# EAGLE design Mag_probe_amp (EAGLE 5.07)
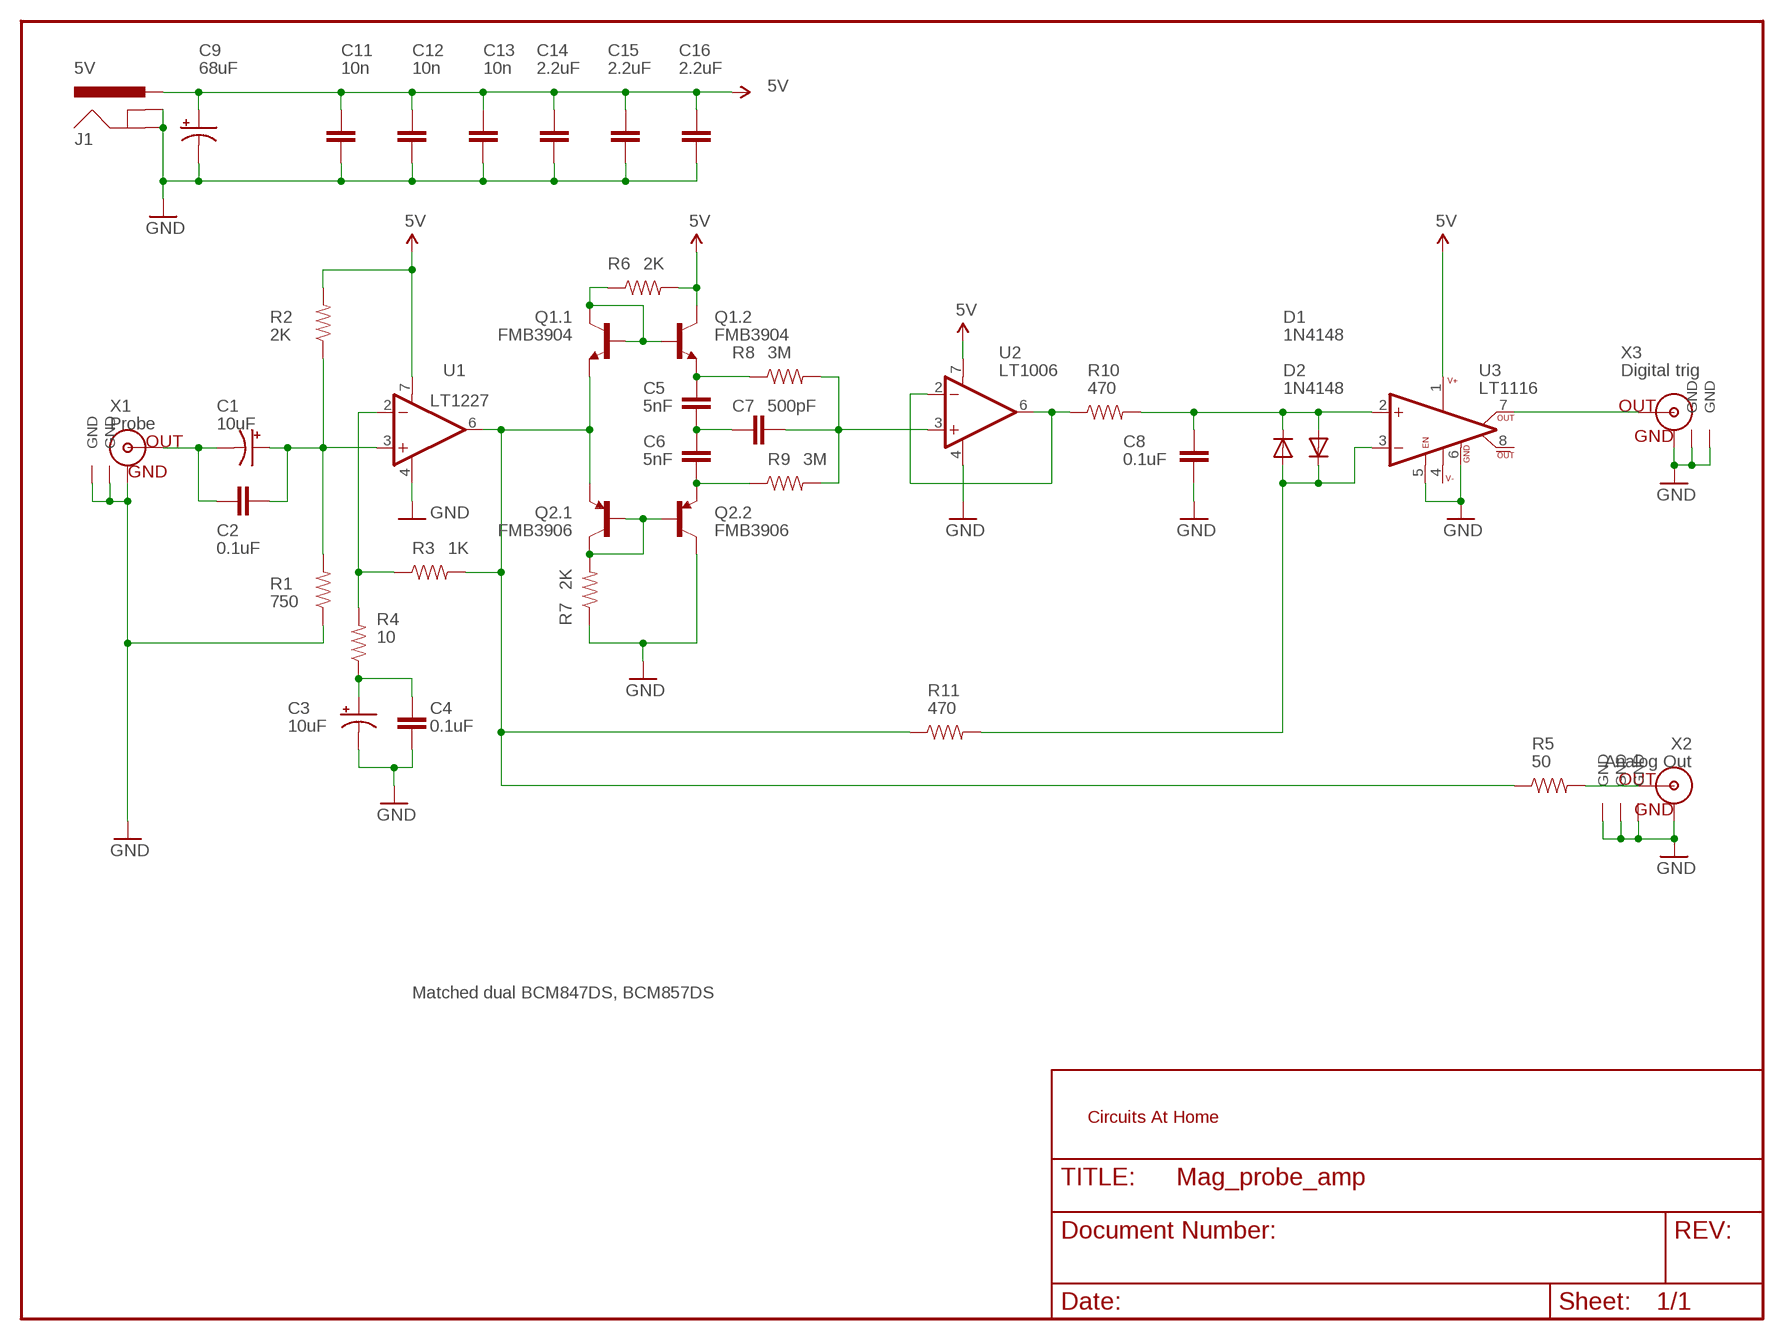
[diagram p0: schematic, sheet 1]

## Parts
C1  10uF  CAP_POL1206  [EIA3216]
C2  0.1uF  CAP1206  [1206]
C3  10uF  CAP_POL1206  [EIA3216]
C4  0.1uF  CAP1206  [1206]
C5  5nF  CAP1206  [1206]
C6  5nF  CAP1206  [1206]
C7  500pF  CAP1206  [1206]
C8  0.1uF  CAP1206  [1206]
C9  68uF  CAP_POL7343  [EIA7343]
C11  10n  CAP1206  [1206]
C12  10n  CAP1206  [1206]
C13  10n  CAP1206  [1206]
C14  2.2uF  CAP1206  [1206]
C15  2.2uF  CAP1206  [1206]
C16  2.2uF  CAP1206  [1206]
D1  1N4148  DIODE-SOD123  [SOD-123]
D2  1N4148  DIODE-SOD123  [SOD-123]
J1  5V  POWER_JACKPTH_LOCK  [POWER_JACK_PTH_LOCK]
Q1  FMB3904  NPN-DUAL-SOT  [SOT23-6]
Q2  FMB3906  PNP-DUAL-SOT  [SOT23-6]
R1  750  RESISTOR1206  [1206]
R2  2K  RESISTOR1206  [1206]
R3  1K  RESISTOR1206  [1206]
R4  10  RESISTOR1206  [1206]
R5  50  RESISTOR1206  [1206]
R6  2K  RESISTOR1206  [1206]
R7  2K  RESISTOR1206  [1206]
R8  3M  RESISTOR1206  [1206]
R9  3M  RESISTOR1206  [1206]
R10  470  RESISTOR1206  [1206]
R11  470  RESISTOR1206  [1206]
U1  LT1227  LT1227_5PIN  [SO08]
U2  LT1006  LT1006_5PIN-SO  [SO08]
U3  LT1116  LT1116_SO8  [SO08]
X1  Probe  BNC-PTHRA  [BNC]
X2  Analog Out  SMB  [SMB_PCB]
X3  Digital trig  BNC-PTHRA  [BNC]

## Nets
5V: C9.A(+) C11.1 C12.1 C13.1 C14.1 C15.1 C16.1 J1.PWR Q1.4(.2:C) R2.2 R6.2 U1.7(V+) U2.7(V+) U3.1(V+)
GND: C3.C(-) C4.2 C8.2 C9.C(-) C11.2 C12.2 C13.2 C14.2 C15.2 C16.2 J1.GND J1.GNDBREAK Q2.4(.2:C) R1.1 R7.1 U1.4(V-) U2.4(V-) U3.5(LA_EN) U3.6(GND) X1.3(GND) X1.4(GND) X1.GND X2.GND1(GND) X2.GND2(GND) X2.GND3(GND) X2.GND4(GND) X3.3(GND) X3.4(GND) X3.GND
N$1: C3.A(+) C4.1 R4.1
N$2: R10.1 U2.2(-) U2.6(OUT)
N$3: R3.1 R4.2 U1.2(-)
N$5: C1.C(-) C2.1 X1.S(OUT)
N$6: R5.2 X2.CENTER(OUT)
N$7: Q1.1(.1:B) Q1.3(.2:B) Q1.6(.1:C) R6.1
N$9: C8.1 D1.K(C) D2.A R10.2 U3.2(+IN)
N$10: D1.A D2.K(C) R11.2 U3.3(-IN)
N$11: Q2.1(.1:B) Q2.3(.2:B) Q2.6(.1:C) R7.2
N$12: U3.7(OUT) X3.S(OUT)
N$13: C5.1 Q1.2(.2:E) R8.1
N$15: C6.2 Q2.2(.2:E) R9.1
N$16: C5.2 C6.1 C7.1
N$17: C7.2 R8.2 R9.2 U2.3(+)
U1_3: C1.A(+) C2.2 R1.2 R2.1 U1.3(+)
U1_6: Q1.5(.1:E) Q2.5(.1:E) R3.2 R5.1 R11.1 U1.6(OUT)
Unconnected: U3.8(!OUT)

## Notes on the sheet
- Matched dual BCM847DS, BCM857DS

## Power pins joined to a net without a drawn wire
V-: U3.4(V-)

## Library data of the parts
C1 C3 C9 = CH_passive:CAP_POL: Capacitor Polarized
C2 C4-C8 C11-C16 = CH_passive:CAP: Capacitor
D1 D2 = CH_semiconductors:DIODE: Diode
J1 = CH_connectors:POWER_JACK: Power Jack This is the standard 5.5mm barrel jack for power. The PTH is the most common, proven, reliable, footprint. All others are experimental. The Slot footprint only works if the mill layer is transmitted to the PCB fab house so be warned. Spark Fun Electronics SKU : PRT-00119. Mating wall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
Q1 = CH_semiconductors:NPN-DUAL: Dual 2N3904 Fairchild FMB3904 SOT23-6 package
Q2 = CH_semiconductors:PNP-DUAL: Dual 2N3906 Fairchild FMB3906
R1-R11 = CH_passive:RESISTOR: Resistor
U1 = CH_Linear_technology:LT1227_5PIN: Linear Technology 140MHz Video Current Feedback Amplifier
U2 = CH_Linear_technology:LT1006_5PIN: LT1006 precision single supply op amp
U3 = CH_Linear_technology:LT1116: LT1116 12ns, Single Supply Ground-Sensing Comparator
X1 X3 = CH_connectors:BNC: BNC Connector, Mouser Part# 5227161
X2 = CH_connectors:SMB

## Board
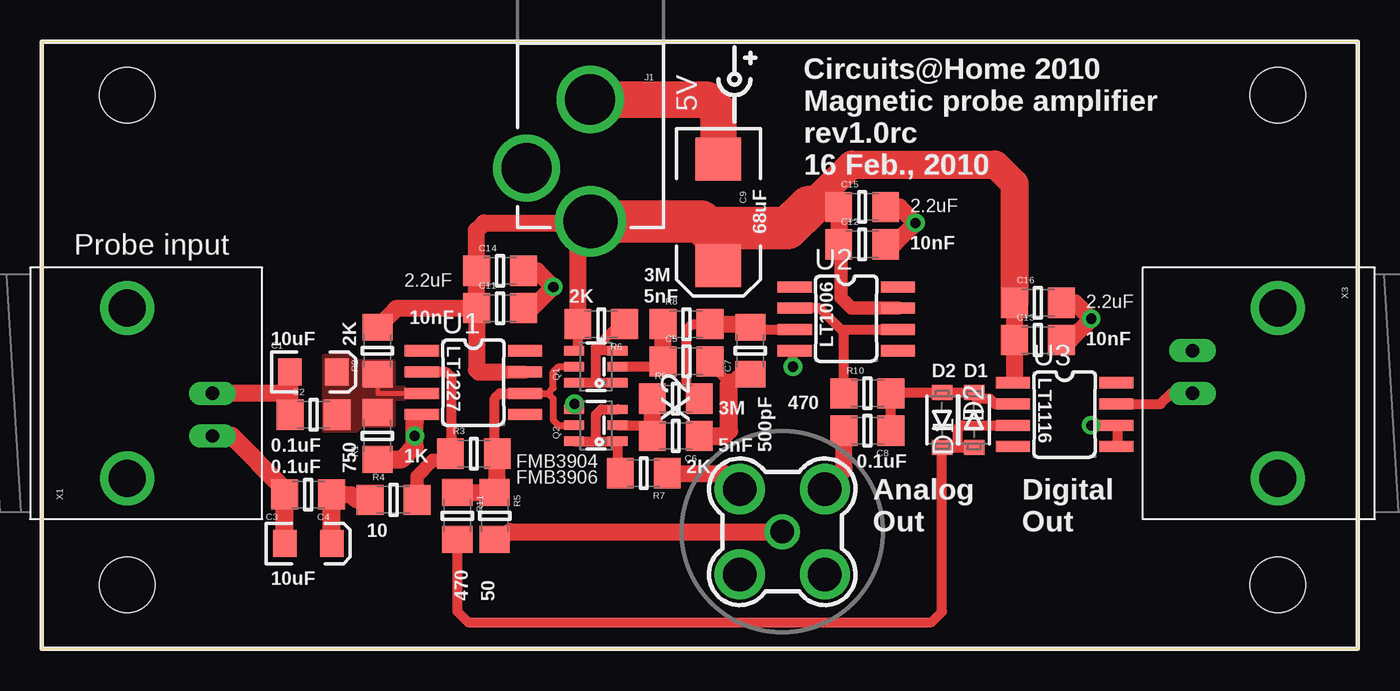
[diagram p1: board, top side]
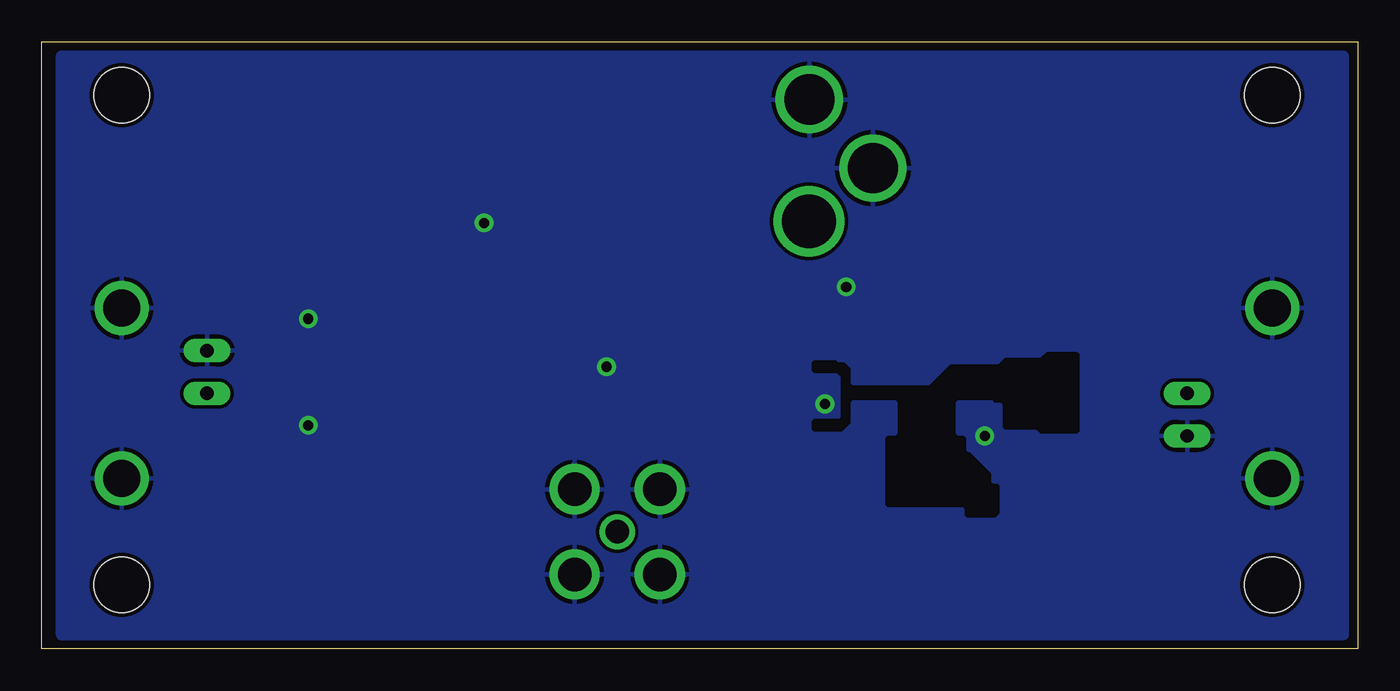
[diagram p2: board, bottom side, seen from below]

Size 78.42 x 36.2 mm. Coordinates in mm from the lower left corner, seen from the top.
Outline: 0,0 78.42,0 78.42,36.2 0,36.2 0,0
Copper layers (1*16): Top 0.035mm / dielectric 1.5mm / Bottom 0.035mm
Design rules "CHome": minimum track width 8mil, minimum drill 20mil, track to track 8mil, track to pad 8mil, pad to pad 8mil, via to via 8mil, smd to smd 8mil, copper to edge 10mil, drill to drill 8mil, minimum pad ring 12mil, minimum via ring 10mil, stop-mask expansion 4mil, vias tented up to drill 25mil, thermal gap 10mil
bRestrict: 68 lines

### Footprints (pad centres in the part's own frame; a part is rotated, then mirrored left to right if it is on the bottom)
EIA3216 = smd 1.4 x 1.6: A 1.4,0; C -1.4,0
1206 = smd 1.6 x 1.8: 1 -1.4,0; 2 1.4,0
EIA7343 = smd 2.55 x 2.7: A 3.17,0; C -3.17,0
SOD-123 = smd 0.91 x 1.22: A -1.635,0; K 1.635,0
POWER_JACK_PTH_LOCK = drill 2.997 round: GND 0.025,6.608; GNDBREAK 3.812,10.7 | drill 3.2 round: PWR 0,13.878
SOT23-6 = smd 0.55 x 1.2: 1 -0.95,-1.3; 2 0,-1.3; 3 0.95,-1.3; 4 0.95,1.3; 5 0,1.3; 6 -0.95,1.3
SO08 = smd 0.66 x 2.032: 1 -1.905,-3.073; 2 -0.635,-3.073; 3 0.635,-3.073; 4 1.905,-3.073; 5 1.905,3.073; 6 0.635,3.073; 7 -0.635,3.073; 8 -1.905,3.073
STAND-OFF = hole 3.302: 0,0
BNC = drill 2.2 round: 3 -5.08,5.08; 4 5.08,5.08 | drill 0.8 long: GND -2.54,0; S 0,0
SMB_PCB = drill 1.4 round: CENTER 0,0 | drill 2 round: GND1 -2.54,2.54; GND2 2.54,2.54; GND3 2.54,-2.54; GND4 -2.54,-2.54

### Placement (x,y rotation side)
C1  16.19,16.51 0 top
C2  16.19,13.97 0 top
C3  15.88,6.29 0 top
C4  15.88,9.21 180 top
C5  38.42,17.14 0 top
C6  37.78,12.7 180 top
C7  42.23,17.78 90 top
C8  49.21,13.02 180 top
C9  40.32,26.04 270 top
C11  27.3,20.32 0 top
C12  48.9,24.13 0 top
C13  59.37,18.41 0 top
C14  27.3,22.54 0 top
C15  48.9,26.35 0 top
C16  59.37,20.64 0 top
D1  55.56,13.65 90 top
D2  53.66,13.65 270 top
J1  32.7,39.37 180 top
Q1  33.02,16.83 90 top
Q2  33.02,13.34 90 top
R1  20,12.7 90 top
R2  20,17.78 90 top
R3  25.74,11.65 0 top
R4  20.95,8.89 0 top
R5  26.99,7.94 270 top
R6  33.34,19.37 180 top
R7  35.88,10.48 180 top
R8  38.42,19.37 0 top
R9  37.78,14.92 0 top
R10  49.21,15.24 0 top
R11  24.77,7.94 270 top
U1  25.72,15.88 270 top
U2  47.94,19.69 270 top
U3  60.96,13.97 270 top
U$1  [STAND-OFF]  5.08,33.02 0 top
U$7  [STAND-OFF]  73.66,3.81 0 top
U$8  [STAND-OFF]  73.66,33.02 0 top
U$9  [STAND-OFF]  5.08,3.81 0 top
X1  10.16,15.24 90 top
X2  44.13,6.99 90 top
X3  68.58,15.24 270 top

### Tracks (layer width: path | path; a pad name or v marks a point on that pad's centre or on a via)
5V
  Top 0.254: 31.94,18 Q1.4
  Top 0.61: U1.7 | R6.2 31.94,18 | 57.97,16.28 arc90 57.89,16.19 U3.1
  Top 0.787: 27.3,16.51 U1.7
  Top 0.813: 47.62,24 47.62,20.96 48.26,20.32 U2.7
  Top 1.016: C11.1 21.25,20.32 arc45 21.07,20.25 R2.2 | C11.1 C14.1 25.91,24.95 26.35,25.4 32.61,25.4 J1.PWR 31.94,24.73 R6.2 | C11.1 25.91,16.64 26.04,16.51 27.3,16.51 | 47.62,24 C12.1 C15.1 45.72,26.35 | C16.1 C13.1 57.97,16.28
  Top 1.676: C16.1 57.97,27.75 56.83,28.89 48.26,28.89 45.72,26.35
  Top 2.54: J1.PWR 39.28,25.49 39.69,25.08 | 39.69,25.08 40.32,24.45 C9.A | 39.69,25.08 44.45,25.08 45.72,26.35
GND  (via drill 0.6)
  Top 0.254: C14.2 28.57,22.54 | 64.14,13.23 U3.6
  Top 0.406: U3.5 arc90 64.14,12.17 | 22.23,13.55 U1.4
  Top 0.61: R1.1 20,11.11 | U3.6 v62.55,13.34 | Q2.4 31.72,14.57 v31.75,14.61 | 64.14,12.17 64.14,13.23 | v44.77,16.83 44.77,17.57 arc-45 44.84,17.75 U2.4
  Top 1.016: X2.GND2 40.64,10.48 R7.1 | 28.57,22.54 29.53,22.54 v30.48,21.59 29.21,20.32 C11.2 | C12.2 50.8,24.13 v52.07,25.4 51.12,26.35 C15.2 50.16,26.35 | C13.2 61.28,18.41 v62.55,19.69 61.59,20.64 C16.2 60.64,20.64 | C8.2 47.81,10.77 arc-45 47.74,10.59 X2.GND3
  Top 1.067: 22.23,13.55 v22.23,12.7 22.23,12.07 21.46,11.3 R1.1 | C3.C C4.2 14.47,9.52 11.3,12.7 X1.GND
  Top 2.184: J1.GND 39.63,32.76 40.32,32.07 C9.C
  pour Bottom: 77.22,35.56 arc-90 77.47,35.31 77.47,0.89 arc-90 77.22,0.63 0.89,0.63 arc-90 0.64,0.89 0.64,35.31 arc-90 0.89,35.56
N$1
  Top 1.016: R4.1 18.73,8.89 18.41,9.21 C4.1
  Top 1.067: C3.A C4.1
N$2
  Top 0.61: 47.62,19.05 U2.6 | 47.62,19.05 46.35,20.32 U2.2 | R10.1 47.81,18.86 47.62,19.05
N$3
  Top 0.406: 24.24,11.23 arc-90 24.45,11.02 | 24.26,11.56 23.94,11.56
  Top 0.61: 24.24,11.23 arc45 24.32,11.41 R3.1 24.34,11.77 arc-45 24.42,11.95 24.42,12.56 | U1.2 24.02,16.51 arc-45 24.2,16.44 24.42,16.22 24.42,12.56 | 24.42,12.56 24.42,12.55
  Top 0.813: 24.24,11.23 23.29,11.23 22.36,10.29 R4.2
  Top 1.067: R3.1 24.26,11.56
N$5
  Top 1.016: C2.1 14.79,15.24 | 14.79,15.24 C1.C | 14.79,15.24 X1.S
N$6
  Top 1.016: X2.CENTER 27.94,6.99 26.86,6.54 R5.2
N$7
  Top 0.254: 34.32,17.81 Q1.3
  Top 0.61: Q1.6 33.03,15.88 | 33.03,15.88 Q1.1 | 33.03,15.88 33.03,17.79 | 34.32,17.81 33.02,17.78 33.03,17.79 | 33.03,17.79 33.03,17.98 34.42,19.37 R6.1
N$9
  Top 0.61: U3.2 56.83,14.61 56.52,14.92 55.68,14.92 D1.K D2.A 50.66,15.29 R10.2 C8.1
N$10
  Top 0.61: 54.61,12.02 D2.K 53.66,2.22 53.02,1.59 25.4,1.59 24.77,2.22 R11.2 | 54.61,12.02 D1.A | U3.3 54.86,13.34 arc90 54.61,13.08 54.61,12.02
N$11
  Top 0.406: 34.32,10.64 R7.2
  Top 0.61: Q2.6 33.02,12.39 | 33.02,12.39 Q2.1 34.32,10.64 | Q2.3 33.34,14.29 33.02,13.97 33.02,12.39
N$12
  Top 0.61: X3.S 67.31,15.24 66.67,14.61 U3.7
N$13
  Top 0.61: Q1.2 36.7,16.83 C5.1
  Top 1.016: C5.1 R8.1
N$15
  Top 0.61: Q2.2 36.38,13.34
  Top 1.016: C6.2 36.38,13.34 R9.1
N$16
  Top 0.61: C5.2 39.82,17.02 40.96,15.88 41.46,16.38 C7.1
  Top 1.067: 40.96,15.88 40.96,13.02 40.64,12.7 C6.1
N$17
  Top 0.61: R9.2 38.42,15.69 38.42,19.05 38.73,19.37 R8.2 39.69,19.5 | U2.3 42.36,19.05 C7.2
  Top 1.016: R8.2 42.04,19.37 C7.2
U1_3
  Top 0.254: U1.3 20,15.24 R2.1
  pour Top (no thermals): 16.83,17.46 16.83,13.02 18.63,13.02 arc45 18.81,13.09 19.05,13.34 20.95,13.34 20.95,14.92 21.59,14.92 21.59,15.56 20.95,15.56 20.95,17.14 19.05,17.14 18.84,17.14 arc-45 18.66,17.22 18.41,17.46
U1_6
  Top 0.254: R3.2 26.57,11.65
  Top 0.406: Q1.5 30.8,16.83 30.48,16.51 30.48,15.56 30.16,15.24 | U1.6 30.16,15.24 | Q2.5 30.8,13.34 30.48,13.65 30.48,14.92 30.16,15.24
  Top 0.61: U1.6 27.3,15.24 26.99,14.92 26.99,12.38 27.14,12.23 R3.2
  Top 1.016: R3.2 27.14,9.49 R5.1 R11.1

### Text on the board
tPlace: Circuits@Home 2010 | 5V | Magnetic probe amplifier | rev1.0rc | 16 Feb., 2010 | 2.2uF | 68uF | Probe input | 10nF | 2.2uF | 3M | LT1006 | 2K | 5nF | 2.2uF | 10nF | 10uF | 2K | LT1227 | 10nF | D2 | D1 | LT1116 | 3M | 470 | 0.1uF | 1K | 5nF | 500pF | 0.1uF | 750 | FMB3904 | 2K | 0.1uF | FMB3906 | Analog | Digital | Out | Out | 10 | 10uF | 470 | 50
